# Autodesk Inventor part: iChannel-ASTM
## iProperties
Author: Administrator
Shininess: 60.0
PropertySet Name: _Private Model Information
Length Units: 11272
Angle Units: 11286
Time Units: 11279
Mass Units: 11290
Length Display Precision: 3
Angle Display Precision: 2
Compacted: True
Created: 2000-10
Part Number: iChannel-ASTM
Material: Steel, Mild
Document SubType Name: Modeling
Designer: Administrator
Description: S10 X 25.4 ASTM S-Beam
Control State: 0
Master: False
Checked Out: False
PropertySet Name: Design Tracking Control
Density: 7.86
Volumn: 1436.7348970937765
Area: 2906.0113824556
PropertySet Name: Model Information
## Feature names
1. Mirror1
